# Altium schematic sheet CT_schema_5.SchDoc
size 371 x 245 mm
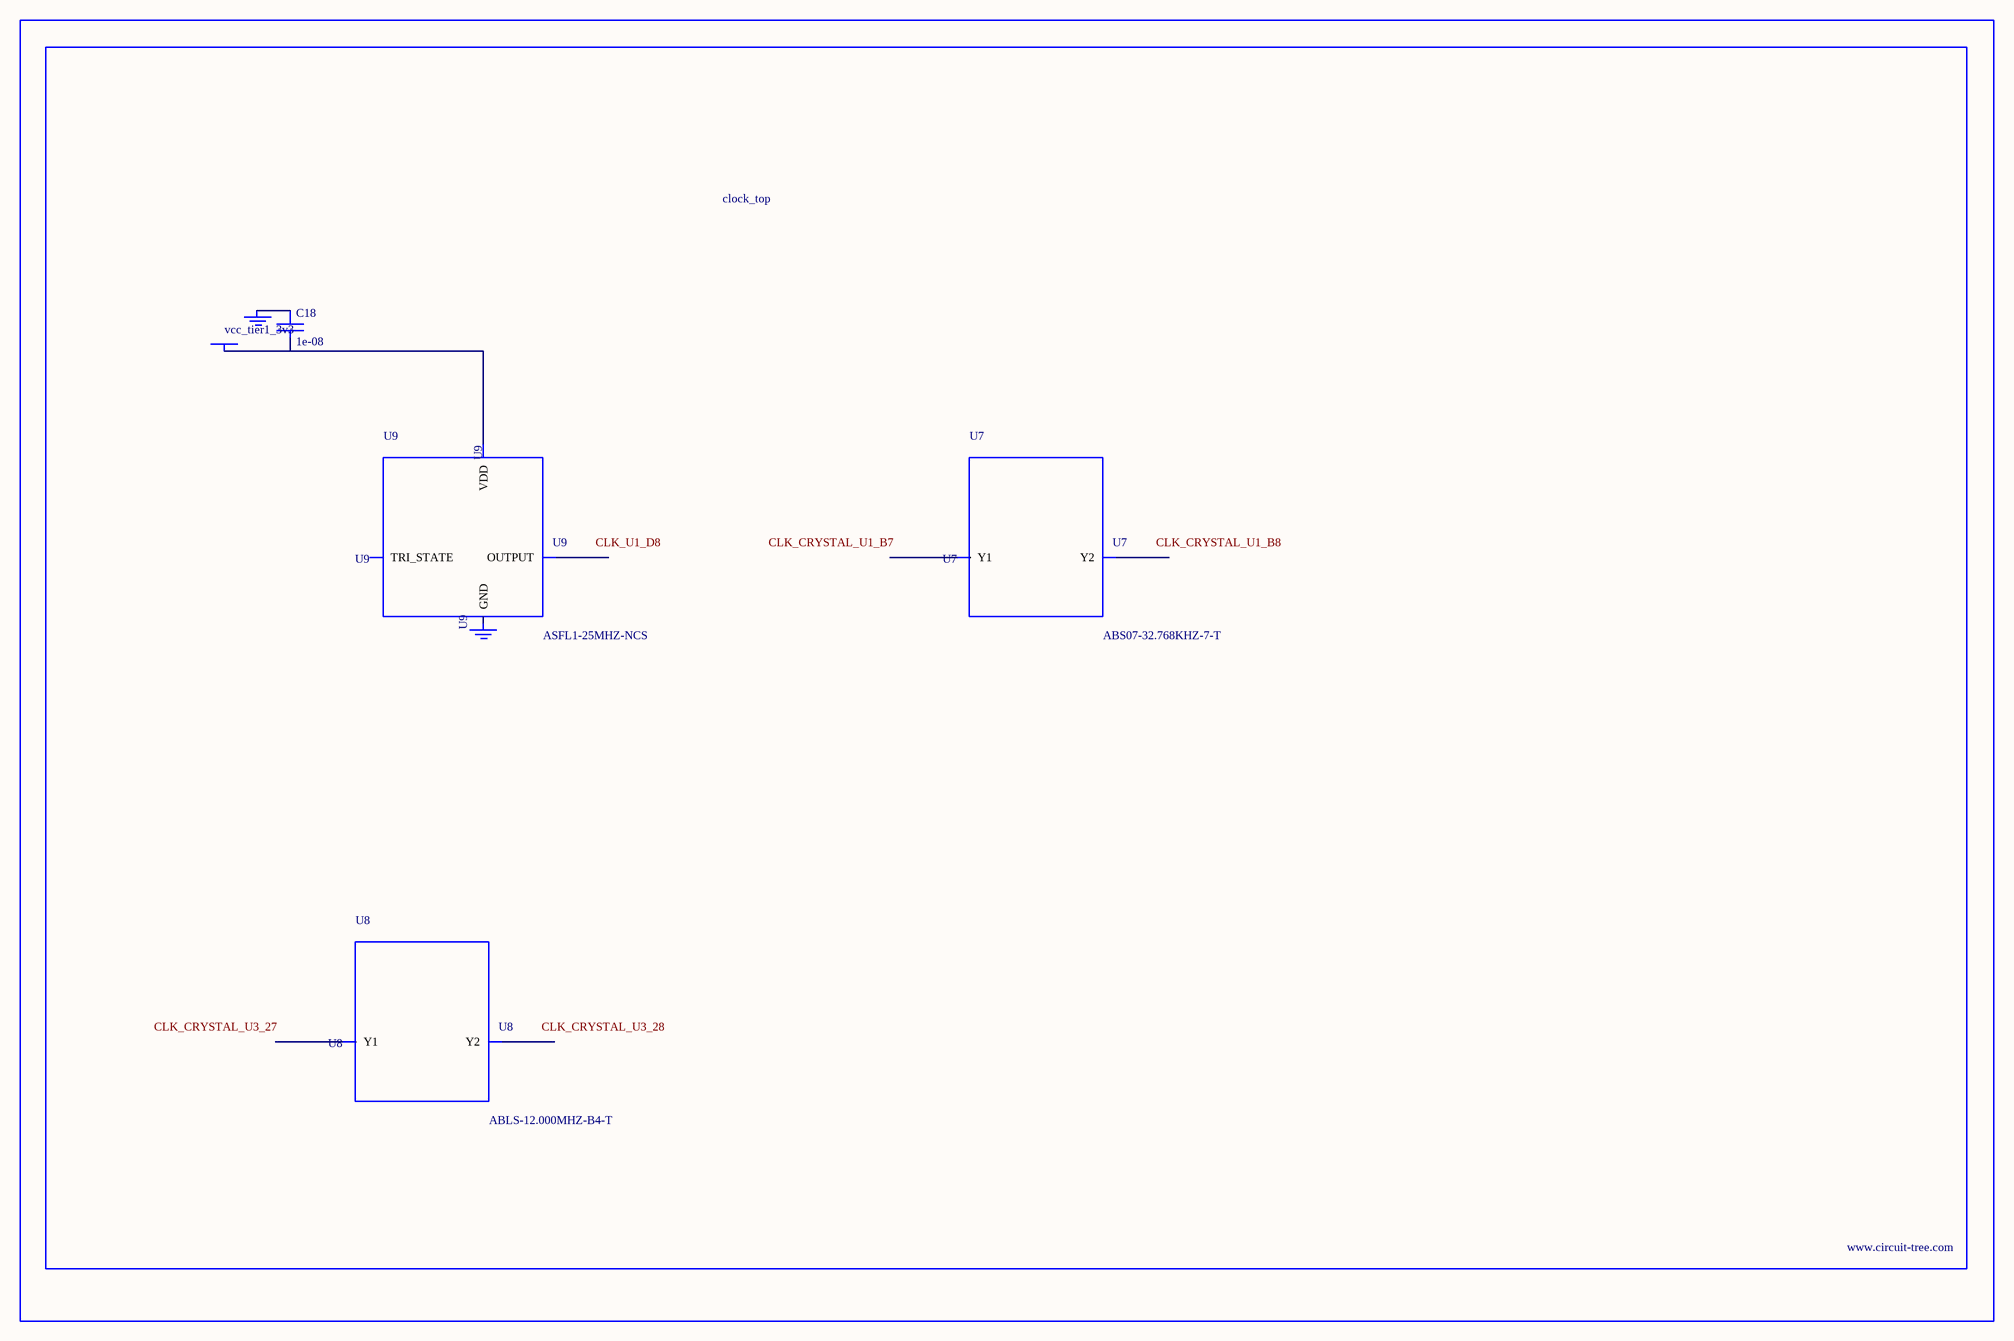
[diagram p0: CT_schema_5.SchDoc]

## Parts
BORDER4  (no value)
C18  1e-08  [C0402]
GND_INSTANCE_4_0  (no value)
GND_INSTANCE_4_1  (no value)
POWER_INSTANCE_4_0  vcc_tier1_3v3
U7  ABS07-32.768KHZ-7-T  [ABS07-32.768KHZ-7-T]
U8  ABLS-12.000MHZ-B4-T  [ABLS-12.000MHZ-B4-T]
U9  ASFL1-25MHZ-NCS  [ASFL1]

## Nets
NetC18_1: C18.1 GND_INSTANCE_4_0.0(GND)
NetC18_2: C18.2 POWER_INSTANCE_4_0.0(PWR) U9.4(VDD)

Not connected (* = marked no-connect by the designer): GND_INSTANCE_4_1 0(GND); U7 1(Y1) 2(Y2); U8 1(Y1) 2(Y2); U9 1(TRI_STATE) 2(GND) 3(OUTPUT)

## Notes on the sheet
- Labels drawn without touching a wire or pin: CLK_CRYSTAL_U1_B7, CLK_CRYSTAL_U1_B8, CLK_CRYSTAL_U3_27, CLK_CRYSTAL_U3_28, CLK_U1_D8

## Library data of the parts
BORDER4 = BORDER_PAGE4
C18 = C0402C103K3RAC
GND_INSTANCE_4_0 GND_INSTANCE_4_1 = GND
POWER_INSTANCE_4_0 = PWR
